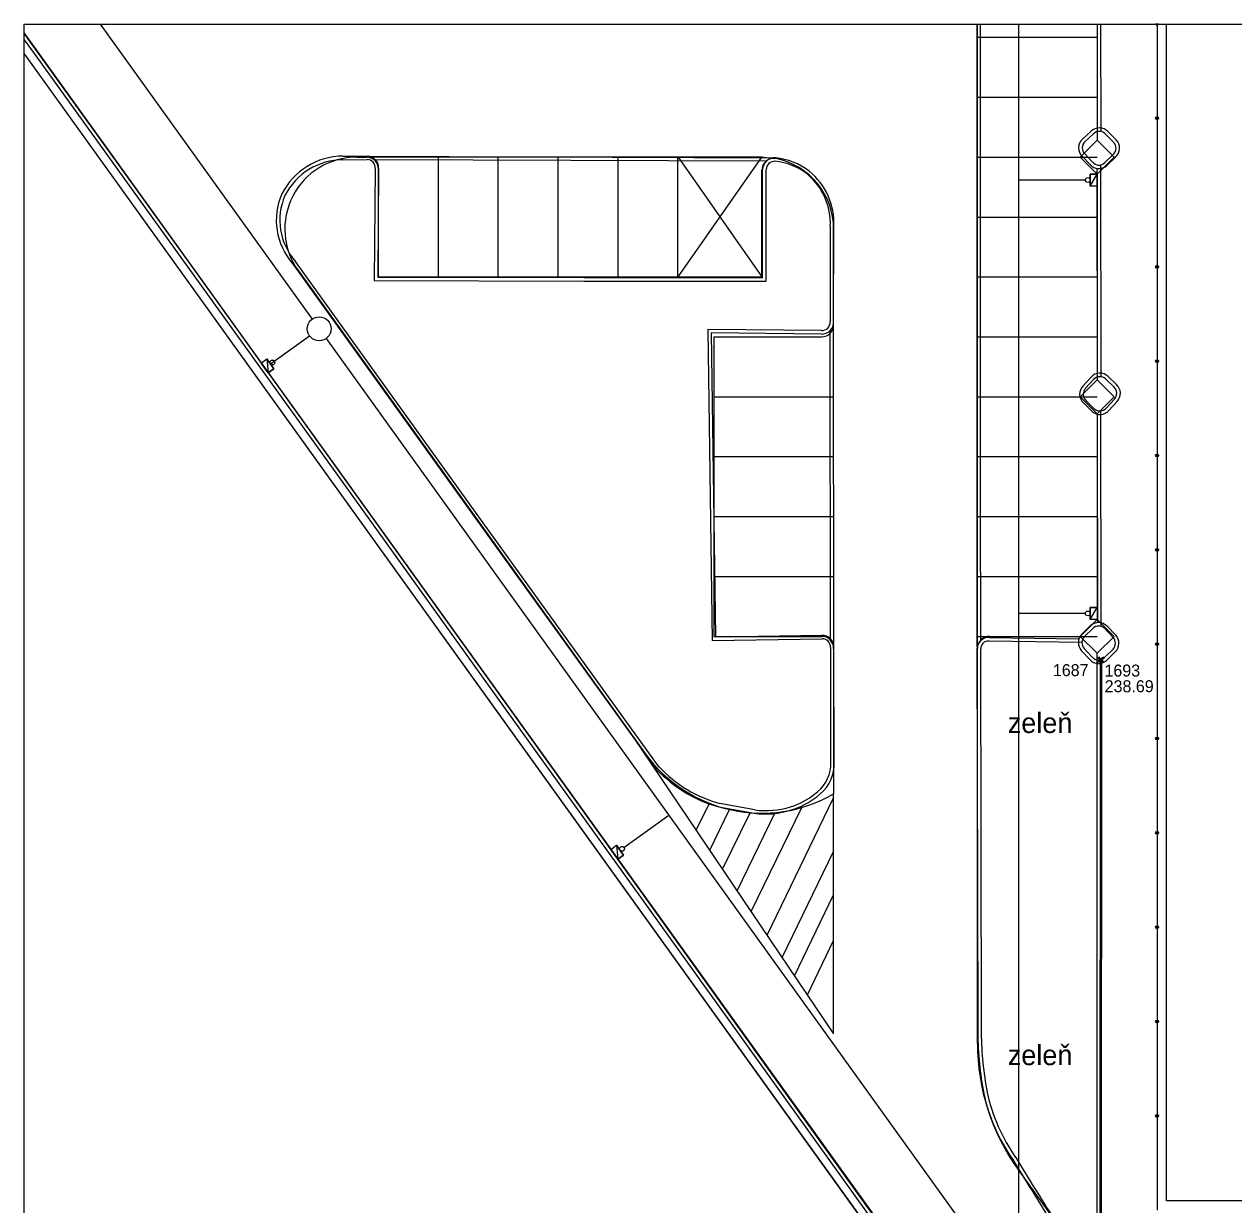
# Model space of a CAD drawing. Extents: x -264165 to -263733, y -1242319 to -1242245.
# Drawn here: x -264165.4 to -264114.9, y -1242294.2 to -1242244.9 of the extents above; entities that cross this region are included whole.
import ezdxf

# ---------------------------------------------------------------- set-up
doc = ezdxf.new("R2010")
doc.units = 0
for name, color, linetype in [('KFA_BOD_CISLO', 7, 'Continuous'), ('KFA_BOD_SYMBOL', 7, 'Continuous'), ('KFA_BOD_VYSKA', 7, 'Continuous'), ('KFA_SO_20-2_OBRUBNIKY_HORNA_HRANA', 7, 'Continuous'), ('POPIS', 7, 'Continuous'), ('PROJEKT_OBRUBNIKY_KOMUNIKACIE', 7, 'Continuous'), ('PROJEKT_TDZ_VODOROVNE', 7, 'Continuous'), ('RAM_NA_TLAC_1-250', 7, 'Continuous'), ('SITUACIA_DSP_2D', 7, 'Continuous'), ('SO_20-3_OBRUBNIKY_DOLNA_HRANA', 7, 'Continuous'), ('SO_20-3_OBRUBNIKY_HORNA_HRANA', 7, 'Continuous')]:
    doc.layers.add(name, color=color, linetype=linetype)

msp = doc.modelspace()

# ---------------------------------------------------------------- linework, layer by layer
at = {"layer": 'KFA_BOD_SYMBOL'}
for p, q in [((-264120.55, -1242271.572), (-264120.329, -1242271.35)), ((-264120.329, -1242271.572), (-264120.55, -1242271.35)), ((-264120.501, -1242271.558), (-264120.28, -1242271.336)), ((-264120.28, -1242271.558), (-264120.501, -1242271.336))]:
    msp.add_line(p, q, dxfattribs=at)
at = {"layer": 'KFA_SO_20-2_OBRUBNIKY_HORNA_HRANA'}
for points in [[(-264120.439, -1242271.461), (-264120.452, -1242296.479), (-264100.511, -1242296.484), (-264083.322, -1242296.485), (-264067.571, -1242296.478), (-264048.312, -1242296.489)], [(-264120.39, -1242271.447), (-264120.403, -1242296.43), (-264100.462, -1242296.435), (-264083.273, -1242296.436), (-264067.522, -1242296.429), (-264048.263, -1242296.44)]]:
    msp.add_lwpolyline(points, dxfattribs=at)
at = {"layer": 'PROJEKT_OBRUBNIKY_KOMUNIKACIE'}
for p, q in [((-264125.568, -1242270.982), (-264125.568, -1242244.935)), ((-264120.568, -1242244.935), (-264120.568, -1242249.774)), ((-264165.363, -1242245.312), (-264119.571, -1242308.982)), ((-264165.363, -1242246.168), (-264115.871, -1242314.982)), ((-264151.48, -1242250.482), (-264151.068, -1242250.482)), ((-264150.568, -1242250.482), (-264151.068, -1242250.482)), ((-264134.568, -1242250.482), (-264150.568, -1242250.482)), ((-264134.581, -1242250.476), (-264134.068, -1242250.533)), ((-264150.568, -1242255.482), (-264150.568, -1242250.982)), ((-264134.568, -1242255.482), (-264134.568, -1242251.033)), ((-264120.568, -1242251.191), (-264120.568, -1242259.775)), ((-264131.568, -1242257.482), (-264131.568, -1242253.482)), ((-264153.916, -1242255.234), (-264139.439, -1242275.363)), ((-264150.568, -1242255.482), (-264134.568, -1242255.482)), ((-264136.568, -1242257.982), (-264136.568, -1242270.482)), ((-264136.568, -1242257.982), (-264132.068, -1242257.982)), ((-264120.568, -1242261.189), (-264120.568, -1242269.774)), ((-264136.568, -1242270.482), (-264132.068, -1242270.482)), ((-264125.068, -1242270.482), (-264121.275, -1242270.482)), ((-264131.568, -1242270.982), (-264131.568, -1242277.056)), ((-264125.568, -1242287.467), (-264125.568, -1242270.982)), ((-264120.568, -1242296.035), (-264120.568, -1242271.189)), ((-264123.874, -1242292.722), (-264120.268, -1242297.737))]:
    msp.add_line(p, q, dxfattribs=at)
for points in [[(-264047.568, -1242244.935), (-264047.568, -1242294.032), (-264117.668, -1242294.032), (-264117.668, -1242244.935)], [(-264165.363, -1242246.168), (-264137.78, -1242284.52), (-264125.581, -1242301.482)], [(-264120.568, -1242249.775), (-264119.861, -1242250.482), (-264120.568, -1242251.189), (-264121.275, -1242250.482), (-264120.568, -1242249.775)], [(-264120.568, -1242259.775), (-264119.861, -1242260.482), (-264120.568, -1242261.189), (-264121.275, -1242260.482), (-264120.568, -1242259.775)], [(-264120.568, -1242269.775), (-264119.861, -1242270.482), (-264120.568, -1242271.189), (-264121.275, -1242270.482), (-264120.568, -1242269.775)]]:
    msp.add_lwpolyline(points, dxfattribs=at)
for centre, radius, start, end in [((-264151.48, -1242253.482), 3, 90, 215.724), ((-264151.068, -1242250.982), 0.5, 0, 90), ((-264134.068, -1242251.033), 0.5, 78.463, 180), ((-264134.568, -1242253.482), 3, 0, 78.463), ((-264132.068, -1242257.482), 0.5, 270, 0), ((-264132.068, -1242270.982), 0.5, 0, 90), ((-264125.068, -1242270.982), 0.5, 90, 180), ((-264134.568, -1242271.86), 6, 215.724, 300), ((-264116.568, -1242287.467), 9, 180, 215.724)]:
    msp.add_arc(centre, radius, start, end, dxfattribs=at)
at = {"layer": 'PROJEKT_TDZ_VODOROVNE'}
for p, q in [((-264125.568, -1242245.482), (-264120.568, -1242245.482)), ((-264125.568, -1242247.982), (-264120.568, -1242247.982)), ((-264148.068, -1242255.482), (-264148.068, -1242250.482)), ((-264145.568, -1242255.482), (-264145.568, -1242250.482)), ((-264143.068, -1242255.482), (-264143.068, -1242250.482)), ((-264140.568, -1242255.482), (-264140.568, -1242250.482)), ((-264138.068, -1242255.482), (-264138.068, -1242250.482)), ((-264134.581, -1242250.484), (-264138.068, -1242255.482)), ((-264138.066, -1242250.484), (-264134.568, -1242255.482)), ((-264125.568, -1242250.482), (-264120.568, -1242250.482)), ((-264125.568, -1242252.982), (-264120.568, -1242252.982)), ((-264125.568, -1242255.482), (-264120.568, -1242255.482)), ((-264125.568, -1242257.982), (-264120.568, -1242257.982)), ((-264136.568, -1242260.482), (-264131.568, -1242260.482)), ((-264125.568, -1242260.482), (-264120.568, -1242260.482)), ((-264136.568, -1242262.982), (-264131.568, -1242262.982)), ((-264125.568, -1242262.982), (-264120.568, -1242262.982)), ((-264136.568, -1242265.482), (-264131.568, -1242265.482)), ((-264125.568, -1242265.482), (-264120.568, -1242265.482)), ((-264136.568, -1242267.982), (-264131.568, -1242267.982)), ((-264125.568, -1242267.982), (-264120.568, -1242267.982)), ((-264125.568, -1242270.482), (-264120.568, -1242270.482)), ((-264137.302, -1242278.57), (-264136.756, -1242277.446)), ((-264134.346, -1242282.947), (-264131.568, -1242277.22)), ((-264136.741, -1242279.401), (-264135.918, -1242277.706)), ((-264136.202, -1242280.199), (-264135.057, -1242277.84)), ((-264135.592, -1242281.102), (-264134.007, -1242277.833)), ((-264135.007, -1242281.969), (-264132.898, -1242277.623)), ((-264133.714, -1242283.883), (-264131.568, -1242279.459)), ((-264133.202, -1242284.642), (-264131.568, -1242281.274)), ((-264132.667, -1242285.434), (-264131.568, -1242283.169))]:
    msp.add_line(p, q, dxfattribs=at)
msp.add_lwpolyline([(-264139.918, -1242274.696), (-264131.568, -1242287.061), (-264131.568, -1242277.056)], dxfattribs=at)
at = {"layer": 'RAM_NA_TLAC_1-250'}
msp.add_lwpolyline([(-264165.363, -1242244.935), (-263732.863, -1242244.935), (-263732.863, -1242319.185), (-264165.363, -1242319.185)], close=True, dxfattribs=at)
at = {"layer": 'SITUACIA_DSP_2D'}
for p, q in [((-264162.189, -1242244.935), (-264153.34, -1242257.238)), ((-264123.854, -1242244.935), (-264123.854, -1242297.736)), ((-264120.568, -1242244.935), (-264120.568, -1242249.774)), ((-264118.01, -1242244.935), (-264118.126, -1242244.935)), ((-264118.068, -1242244.98), (-264118.068, -1242244.935)), ((-264118.068, -1242244.935), (-264118.068, -1242294.432)), ((-264117.668, -1242294.032), (-264117.668, -1242244.935)), ((-264165.363, -1242245.312), (-264119.75, -1242308.732)), ((-264165.363, -1242246.168), (-264115.871, -1242314.982)), ((-264118.008, -1242248.857), (-264118.128, -1242248.857)), ((-264118.068, -1242248.917), (-264118.068, -1242248.797)), ((-264151.48, -1242250.482), (-264151.068, -1242250.482)), ((-264150.568, -1242255.482), (-264150.568, -1242250.982)), ((-264134.568, -1242255.482), (-264134.568, -1242251.033)), ((-264120.857, -1242251.689), (-264120.857, -1242251.189)), ((-264120.857, -1242251.189), (-264120.567, -1242251.189)), ((-264120.857, -1242251.689), (-264120.567, -1242251.189)), ((-264120.857, -1242251.689), (-264120.567, -1242251.189)), ((-264120.567, -1242251.189), (-264120.857, -1242251.189)), ((-264120.857, -1242251.189), (-264120.857, -1242251.689)), ((-264120.568, -1242251.191), (-264120.568, -1242259.775)), ((-264120.567, -1242251.189), (-264120.567, -1242251.689)), ((-264121.057, -1242251.439), (-264123.853, -1242251.439)), ((-264120.567, -1242251.689), (-264120.857, -1242251.689)), ((-264131.568, -1242257.482), (-264131.568, -1242253.482)), ((-264153.916, -1242255.234), (-264139.439, -1242275.363)), ((-264118.008, -1242255.057), (-264118.128, -1242255.057)), ((-264118.068, -1242255.117), (-264118.068, -1242254.997)), ((-264150.568, -1242255.482), (-264134.568, -1242255.482)), ((-264155.084, -1242259.108), (-264153.454, -1242257.936)), ((-264154.921, -1242258.991), (-264153.454, -1242257.936)), ((-264152.757, -1242258.05), (-264124.146, -1242297.83)), ((-264152.757, -1242258.05), (-264124.146, -1242297.83)), ((-264136.568, -1242257.982), (-264136.568, -1242270.482)), ((-264136.568, -1242257.982), (-264132.068, -1242257.982)), ((-264155.465, -1242259.074), (-264155.23, -1242258.905)), ((-264155.173, -1242259.48), (-264155.465, -1242259.074)), ((-264155.23, -1242258.905), (-264154.938, -1242259.311)), ((-264155.23, -1242258.905), (-264155.173, -1242259.48)), ((-264155.23, -1242258.905), (-264155.173, -1242259.48)), ((-264154.938, -1242259.311), (-264155.23, -1242258.905)), ((-264154.938, -1242259.311), (-264155.173, -1242259.48)), ((-264155.173, -1242259.48), (-264154.938, -1242259.311)), ((-264118.008, -1242258.995), (-264118.128, -1242258.995)), ((-264118.068, -1242259.055), (-264118.068, -1242258.935)), ((-264120.568, -1242261.189), (-264120.568, -1242269.774)), ((-264118.068, -1242262.992), (-264118.068, -1242262.872)), ((-264118.008, -1242262.932), (-264118.128, -1242262.932)), ((-264118.008, -1242266.87), (-264118.128, -1242266.87)), ((-264118.068, -1242266.93), (-264118.068, -1242266.81)), ((-264120.857, -1242269.775), (-264120.857, -1242269.275)), ((-264120.857, -1242269.275), (-264120.567, -1242269.275)), ((-264120.857, -1242269.775), (-264120.567, -1242269.275)), ((-264120.857, -1242269.775), (-264120.567, -1242269.275)), ((-264120.567, -1242269.275), (-264120.857, -1242269.275)), ((-264120.857, -1242269.275), (-264120.857, -1242269.775)), ((-264120.567, -1242269.275), (-264120.567, -1242269.775)), ((-264121.058, -1242269.525), (-264123.854, -1242269.525)), ((-264120.567, -1242269.775), (-264120.857, -1242269.775)), ((-264136.568, -1242270.482), (-264132.068, -1242270.482)), ((-264125.068, -1242270.482), (-264121.275, -1242270.482)), ((-264131.568, -1242270.982), (-264131.568, -1242277.056)), ((-264125.568, -1242287.467), (-264125.568, -1242270.982)), ((-264118.008, -1242270.807), (-264118.128, -1242270.807)), ((-264118.068, -1242270.867), (-264118.068, -1242270.747)), ((-264118.008, -1242274.745), (-264118.128, -1242274.745)), ((-264118.068, -1242274.805), (-264118.068, -1242274.685)), ((-264140.324, -1242279.287), (-264138.451, -1242277.94)), ((-264118.008, -1242278.682), (-264118.128, -1242278.682)), ((-264118.068, -1242278.742), (-264118.068, -1242278.622)), ((-264140.868, -1242279.37), (-264140.632, -1242279.201)), ((-264140.576, -1242279.776), (-264140.868, -1242279.37)), ((-264140.632, -1242279.201), (-264140.341, -1242279.607)), ((-264140.632, -1242279.201), (-264140.576, -1242279.776)), ((-264140.632, -1242279.201), (-264140.576, -1242279.776)), ((-264140.341, -1242279.607), (-264140.632, -1242279.201)), ((-264140.341, -1242279.607), (-264140.576, -1242279.776)), ((-264140.576, -1242279.776), (-264140.341, -1242279.607)), ((-264118.068, -1242282.68), (-264118.068, -1242282.56)), ((-264118.008, -1242282.62), (-264118.128, -1242282.62)), ((-264118.008, -1242286.557), (-264118.128, -1242286.557)), ((-264118.068, -1242286.617), (-264118.068, -1242286.497)), ((-264118.008, -1242290.495), (-264118.128, -1242290.495)), ((-264118.068, -1242290.555), (-264118.068, -1242290.435)), ((-264123.874, -1242292.722), (-264120.268, -1242297.737)), ((-264047.568, -1242294.032), (-264117.668, -1242294.032))]:
    msp.add_line(p, q, dxfattribs=at)
for points in [[(-264165.363, -1242246.168), (-264137.78, -1242284.52), (-264125.581, -1242301.482)], [(-264120.568, -1242296.035), (-264120.568, -1242271.189), (-264120.568, -1242271.189)]]:
    msp.add_lwpolyline(points, dxfattribs=at)
for points in [[(-264120.568, -1242249.775), (-264119.861, -1242250.482), (-264120.568, -1242251.189), (-264121.275, -1242250.482)], [(-264120.568, -1242259.775), (-264119.861, -1242260.482), (-264120.568, -1242261.189), (-264121.275, -1242260.482)], [(-264120.568, -1242269.775), (-264119.861, -1242270.482), (-264120.568, -1242271.189), (-264121.275, -1242270.482)]]:
    msp.add_lwpolyline(points, close=True, dxfattribs=at)
for centre, radius in [((-264118.068, -1242248.857), 0.06), ((-264120.957, -1242251.439), 0.1), ((-264118.068, -1242255.057), 0.06), ((-264153.049, -1242257.644), 0.5), ((-264155, -1242259.053), 0.1), ((-264118.068, -1242258.995), 0.06), ((-264118.068, -1242262.932), 0.06), ((-264118.068, -1242266.87), 0.06), ((-264120.958, -1242269.525), 0.1), ((-264118.068, -1242270.807), 0.06), ((-264118.068, -1242274.745), 0.06), ((-264118.068, -1242278.682), 0.06), ((-264140.403, -1242279.349), 0.1), ((-264118.068, -1242282.62), 0.06), ((-264118.068, -1242286.557), 0.06), ((-264118.068, -1242290.495), 0.06)]:
    msp.add_circle(centre, radius, dxfattribs=at)
for centre, radius, start, end in [((-264118.068, -1242244.92), 0.06, 194.9361, 345.0639), ((-264151.48, -1242253.482), 3, 90, 215.724), ((-264151.068, -1242250.982), 0.5, 0, 90), ((-264134.068, -1242251.033), 0.5, 78.463, 180), ((-264134.568, -1242253.482), 3, 0, 78.463), ((-264132.068, -1242257.482), 0.5, 270, 0), ((-264132.068, -1242270.982), 0.5, 0, 90), ((-264125.068, -1242270.982), 0.5, 90, 180), ((-264134.568, -1242271.86), 6, 215.724, 300), ((-264116.568, -1242287.467), 9, 180, 215.724)]:
    msp.add_arc(centre, radius, start, end, dxfattribs=at)
at = {"layer": 'SO_20-3_OBRUBNIKY_DOLNA_HRANA'}
for p, q in [((-264120.55, -1242249.265), (-264120.552, -1242244.935)), ((-264121.182, -1242249.732), (-264120.824, -1242249.4)), ((-264120.115, -1242249.418), (-264119.77, -1242249.765)), ((-264152.061, -1242250.436), (-264151.031, -1242250.44)), ((-264151.031, -1242250.44), (-264133.997, -1242250.51)), ((-264134.384, -1242250.654), (-264150.7, -1242250.592)), ((-264120.864, -1242250.796), (-264121.194, -1242250.445)), ((-264119.796, -1242250.48), (-264120.161, -1242250.829)), ((-264120.548, -1242259.507), (-264120.56, -1242250.957)), ((-264131.568, -1242257.353), (-264131.563, -1242253.368)), ((-264131.555, -1242270.935), (-264131.568, -1242257.353)), ((-264131.701, -1242270.58), (-264131.718, -1242257.725)), ((-264121.162, -1242260.036), (-264120.821, -1242259.664)), ((-264120.107, -1242259.637), (-264119.754, -1242259.976)), ((-264120.776, -1242261.096), (-264121.139, -1242260.741)), ((-264119.736, -1242260.68), (-264120.077, -1242261.051)), ((-264120.537, -1242269.907), (-264120.555, -1242261.209)), ((-264121.2, -1242270.383), (-264120.854, -1242270.048)), ((-264120.152, -1242270.058), (-264119.792, -1242270.425)), ((-264131.548, -1242275.925), (-264131.555, -1242270.935)), ((-264125.077, -1242270.527), (-264121.327, -1242270.585)), ((-264120.878, -1242271.452), (-264121.216, -1242271.082)), ((-264119.815, -1242271.131), (-264120.176, -1242271.488)), ((-264136.366, -1242277.6), (-264134.891, -1242277.863))]:
    msp.add_line(p, q, dxfattribs=at)
for points in [[(-264125.573, -1242270.915), (-264125.578, -1242264.895), (-264125.575, -1242255.299), (-264125.581, -1242244.935)], [(-264125.429, -1242270.662), (-264125.437, -1242264.9), (-264125.431, -1242255.315), (-264125.435, -1242244.935)], [(-264165.363, -1242245.338), (-264164.83, -1242246.079), (-264158.406, -1242254.997), (-264151.981, -1242263.929), (-264145.549, -1242272.885), (-264139.496, -1242281.305), (-264132.148, -1242291.541), (-264125.165, -1242301.265), (-264124.808, -1242301.762)], [(-264150.565, -1242250.962), (-264150.603, -1242255.49), (-264142.001, -1242255.509), (-264134.535, -1242255.513), (-264134.532, -1242250.999)], [(-264154.16, -1242254.916), (-264146.578, -1242265.475), (-264138.972, -1242276.017)], [(-264132.075, -1242257.867), (-264136.682, -1242257.821), (-264136.502, -1242270.502), (-264132.063, -1242270.435)], [(-264125.585, -1242271.017), (-264125.561, -1242281.034), (-264125.551, -1242287.051)]]:
    msp.add_lwpolyline(points, dxfattribs=at)
for centre, major_axis, ratio, start_param, end_param in [((-264120.478, -1242249.757), (-0.496, 0.013), 0.999976, 3.917165, 5.507613), ((-264120.853, -1242250.094), (-0.008, -0.489), 0.99979, 3.896384, 5.528394), ((-264120.125, -1242250.11), (-0.05, 0.493), 0.999948, 3.767556, 5.382488), ((-264152.024, -1242253.339), (-2.883, -0.344), 0.999969, 4.606334, 5.69177), ((-264151.057, -1242250.932), (-0.491, -0.041), 0.999, 2.997109, 4.577664), ((-264134.031, -1242251.011), (0.088, -0.494), 0.999099, 2.898819, 4.51404), ((-264134.272, -1242253.247), (-2.666, -0.684), 0.999354, 3.804651, 4.361234), ((-264134.328, -1242253.225), (2.694, 0.641), 0.999979, 5.998124, 6.942783), ((-264120.496, -1242250.47), (0.231, 0.434), 0.99998, 2.785165, 4.380766), ((-264152.113, -1242253.114), (-0.18, -2.722), 0.999297, 4.364774, 5.499982), ((-264132.067, -1242257.368), (0.351, 0.355), 0.999602, 3.903953, 5.520825), ((-264120.451, -1242259.991), (-0.446, 0.213), 0.999982, 4.387078, 6.003781), ((-264120.802, -1242260.377), (-0.169, -0.466), 0.999971, 4.300812, 5.883738), ((-264120.094, -1242260.337), (-0.243, 0.432), 0.999885, 3.436393, 5.015373), ((-264120.449, -1242260.728), (0.434, 0.234), 0.999977, 3.491254, 5.073033), ((-264120.508, -1242270.4), (-0.425, 0.251), 0.999963, 4.439778, 6.021899), ((-264132.051, -1242270.931), (-0.496, -0.002), 0.999873, 3.129279, 4.731059), ((-264120.856, -1242270.741), (0.329, -0.372), 0.999965, 3.183838, 4.746565), ((-264120.161, -1242270.766), (-0.26, 0.43), 0.999916, 3.356902, 4.915899), ((-264125.088, -1242271.024), (-0.497, -0.011), 0.999893, 4.66727, 6.246237), ((-264120.508, -1242271.108), (0.496, -0.095), 0.999785, 4.080051, 5.620303), ((-264134.793, -1242272.072), (1.661, -5.503), 0.999756, 5.175839, 5.71277), ((-264133.222, -1242275.788), (1.449, 0.851), 0.998406, 4.780647, 5.669539), ((-264134.142, -1242274.881), (2.533, 1.525), 0.999647, 4.445425, 4.853802), ((-264134.422, -1242274.319), (0.823, -3.479), 0.999728, 5.919135, 6.358584), ((-264111.36, -1242286.915), (1.586, -14.312), 0.985444, 4.613033, 4.788424), ((-264117.781, -1242287.891), (3.336, -6.944), 0.999948, 4.482958, 4.876448), ((-263998.852, -1242215.853), (84.302, -140.139), 0.897217, 4.7183, 4.736655)]:
    msp.add_ellipse(centre, major_axis=major_axis, ratio=ratio, start_param=start_param, end_param=end_param, dxfattribs=at)
at = {"layer": 'SO_20-3_OBRUBNIKY_HORNA_HRANA'}
for p, q in [((-264120.405, -1242249.415), (-264120.408, -1242244.935)), ((-264121.082, -1242249.84), (-264120.725, -1242249.508)), ((-264120.214, -1242249.524), (-264119.873, -1242249.869)), ((-264152.059, -1242250.59), (-264151.046, -1242250.584)), ((-264120.755, -1242250.692), (-264121.086, -1242250.341)), ((-264119.899, -1242250.378), (-264120.258, -1242250.724)), ((-264120.405, -1242259.649), (-264120.42, -1242250.808)), ((-264131.709, -1242253.369), (-264131.713, -1242257.356)), ((-264121.047, -1242260.125), (-264120.713, -1242259.765)), ((-264120.216, -1242259.735), (-264119.858, -1242260.085)), ((-264120.685, -1242260.983), (-264121.038, -1242260.637)), ((-264119.847, -1242260.582), (-264120.184, -1242260.951)), ((-264120.399, -1242270.064), (-264120.411, -1242261.068)), ((-264120.754, -1242270.154), (-264121.096, -1242270.487)), ((-264119.903, -1242270.522), (-264120.249, -1242270.157)), ((-264131.7, -1242270.94), (-264131.693, -1242275.925)), ((-264121.203, -1242270.732), (-264125.076, -1242270.677)), ((-264121.105, -1242270.988), (-264120.769, -1242271.346)), ((-264125.435, -1242271.03), (-264125.41, -1242287.033)), ((-264120.272, -1242271.377), (-264119.904, -1242271.02)), ((-264134.865, -1242277.726), (-264136.32, -1242277.458))]:
    msp.add_line(p, q, dxfattribs=at)
for points in [[(-264165.363, -1242245.587), (-264164.951, -1242246.159), (-264158.525, -1242255.075), (-264152.106, -1242264.005), (-264145.671, -1242272.964), (-264139.631, -1242281.361), (-264132.272, -1242291.613), (-264125.285, -1242301.347), (-264124.926, -1242301.846)], [(-264150.712, -1242250.956), (-264150.75, -1242255.637), (-264142.004, -1242255.656), (-264134.386, -1242255.657), (-264134.384, -1242251.001)], [(-264138.851, -1242275.933), (-264146.457, -1242265.393), (-264154.039, -1242254.835)], [(-264132.075, -1242257.722), (-264136.822, -1242257.676), (-264136.642, -1242270.651), (-264132.052, -1242270.581)]]:
    msp.add_lwpolyline(points, dxfattribs=at)
for centre, major_axis, ratio, start_param, end_param in [((-264120.477, -1242249.764), (-0.351, 0.062), 0.999629, 4.05561, 5.657259), ((-264120.842, -1242250.092), (-0.081, -0.339), 0.999363, 4.135616, 5.740237), ((-264120.132, -1242250.111), (0.001, 0.354), 0.999133, 3.862601, 5.467869), ((-264152.043, -1242253.317), (-2.497, -1.096), 0.999987, 4.304573, 5.400072), ((-264151.055, -1242250.928), (0.139, 0.315), 0.999759, 5.044982, 6.672118), ((-264134.033, -1242251.008), (0.028, -0.35), 0.998731, 3.005691, 4.612609), ((-264134.256, -1242253.224), (-2.407, -0.927), 0.999506, 3.680289, 4.250966), ((-264120.491, -1242250.471), (0.337, 0.069), 0.999736, 3.638527, 5.255914), ((-264134.38, -1242253.246), (0.97, 2.492), 0.999929, 5.037359, 5.95793), ((-264152.103, -1242253.117), (-0.276, -2.575), 0.999205, 4.408329, 5.5446), ((-264132.073, -1242257.362), (0.342, 0.112), 0.999272, 4.390828, 5.985608), ((-264120.45, -1242259.996), (-0.35, 0.016), 0.999265, 4.028104, 5.60664), ((-264120.788, -1242260.377), (-0.024, -0.36), 0.999723, 4.006897, 5.58404), ((-264120.099, -1242260.339), (-0.008, 0.35), 0.99958, 3.923297, 5.501481), ((-264120.45, -1242260.713), (0.344, 0.097), 0.99713, 3.722556, 5.278139), ((-264120.846, -1242270.742), (-0.042, 0.355), 0.999563, 0.658118, 2.212755), ((-264120.503, -1242270.4), (-0.32, 0.145), 0.999953, 4.331761, 5.933159), ((-264132.048, -1242270.929), (0.258, -0.233), 0.999459, 0.702378, 2.318149), ((-264125.096, -1242271.016), (-0.126, -0.315), 0.999014, 3.461931, 5.134146), ((-264120.16, -1242270.77), (0.045, -0.355), 0.9995, 0.673162, 2.21368), ((-264120.505, -1242271.12), (-0.347, -0.014), 0.99922, 0.669975, 2.267851), ((-264134.867, -1242272.183), (-0.221, -5.466), 0.999887, 5.50793, 6.054882), ((-264133.2, -1242275.804), (1.245, 0.861), 0.996982, 4.693871, 5.596569), ((-264134.185, -1242274.837), (2.588, 1.292), 0.993304, 4.536396, 4.933863), ((-264134.431, -1242274.144), (-0.647, -3.55), 0.999738, 0.059669, 0.477357), ((-264110.542, -1242286.806), (1.637, -14.996), 0.985568, 4.620267, 4.785533), ((-264117.568, -1242287.8), (2.992, -7.193), 0.999392, 4.539799, 4.923581), ((-264058.218, -1242251.717), (75.932, -123.334), 0.533241, 4.712594, 4.733384)]:
    msp.add_ellipse(centre, major_axis=major_axis, ratio=ratio, start_param=start_param, end_param=end_param, dxfattribs=at)

# ---------------------------------------------------------------- texts
at = {"layer": 'KFA_BOD_CISLO'}
for s, p in [('1687', (-264122.415, -1242272.141)), ('1693', (-264120.261, -1242272.158))]:
    msp.add_text(s, height=0.5, dxfattribs=at).set_placement(p)
at = {"layer": 'KFA_BOD_VYSKA'}
msp.add_text('238.69', height=0.5, dxfattribs=at).set_placement((-264120.253, -1242272.813))
at = {"layer": 'POPIS'}
for p in [(-264124.298, -1242274.514), (-264124.298, -1242288.375)]:
    msp.add_text('zeleň', height=0.8438, dxfattribs=at).set_placement(p)

doc.saveas('drawing.dxf')
